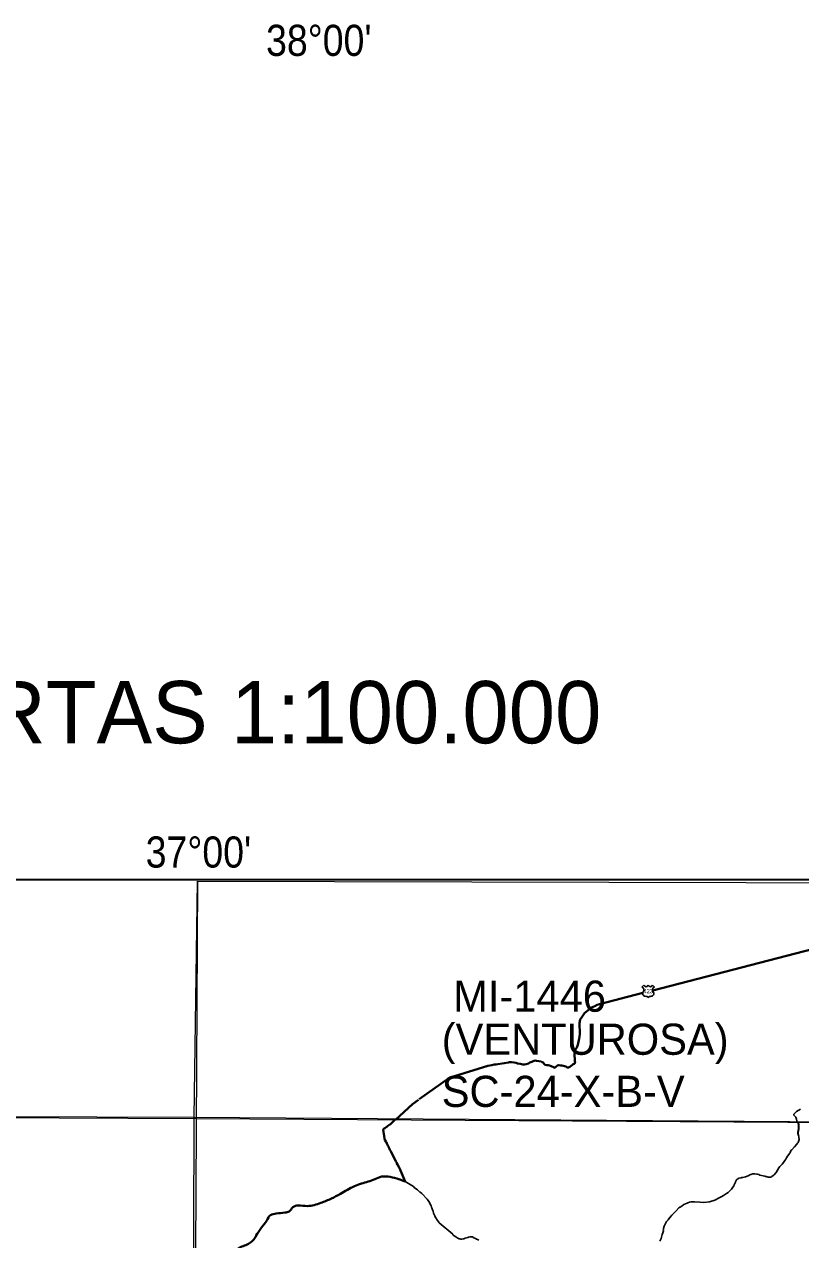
# Model space of a CAD drawing. Extents: x 553962 to 842807, y 8883888 to 9032388.
# Drawn here: x 604874 to 617340, y 8918990 to 8938500 of the extents above; entities that cross this region are included whole.
import ezdxf
from ezdxf.enums import TextEntityAlignment as Align

# ---------------------------------------------------------------- set-up
doc = ezdxf.new("R2010")
doc.units = 0
doc.header["$LTSCALE"] = 150
doc.layers.add('46', color=7, linetype='Continuous')
doc.layers.add('6', color=7, linetype='Continuous', lineweight=13)

msp = doc.modelspace()

# ---------------------------------------------------------------- linework, layer by layer
at = {"layer": '6', "lineweight": 25}
for p, q in [((614790.2, 8923043.1), (614822.1, 8923075.1)), ((614962, 8923075.1), (614994, 8923043.1))]:
    msp.add_line(p, q, dxfattribs=at)
at = {"layer": '6', "lineweight": 35}
msp.add_lwpolyline([(574695.3, 8924769.6), (626625.7, 8924769.6), (626625.7, 8896026.7), (574695.3, 8896026.7)], close=True, dxfattribs=at)
at = {"layer": '6'}
for points in [[(607657.7, 8924743.3), (607574.2, 8909874.9), (607492.3, 8896026.7)], [(574684.9, 8921064.7), (596639.8, 8920989.8), (607636.3, 8920937.2), (626625.7, 8920820.5)], [(608653.2, 8919135.4), (608627.5, 8919108.1), (608598.7, 8919080.5), (608588.5, 8919064.1), (608579.3, 8919042.5), (608574.7, 8919033.7)]]:
    msp.add_lwpolyline(points, dxfattribs=at)
for points in [[(607657.7, 8924743.3), (618663, 8924716.1), (618636, 8920869.6), (607600.8, 8920952.4)], [(607600.8, 8920952.4), (596639.8, 8920989.8), (596608.8, 8909934.4), (607569.8, 8909894.9)]]:
    msp.add_lwpolyline(points, close=True, dxfattribs=at)
at = {"layer": '6', "lineweight": 40}
for points in [[(614964.2, 8922992.9), (617832.6, 8923732.6)], [(611214.5, 8921246.7), (611690.9, 8921581.7), (611739.2, 8921604.7), (611780.6, 8921615.4), (612315.8, 8921783.7), (612380.5, 8921791.8), (612418.8, 8921801.5), (612446.2, 8921801.9), (612579.5, 8921823.3), (612649.2, 8921836.5), (612665.4, 8921838.8), (612696.8, 8921839.3), (612734.3, 8921834.8), (612769.8, 8921828.3), (612794.3, 8921820.6), (612836.9, 8921811.2), (612878.6, 8921802.8), (612904.9, 8921800.2), (612931.2, 8921805.6), (612968.5, 8921819.4), (612991.5, 8921833.9), (613020.7, 8921847.5), (613043.9, 8921853.9), (613078.2, 8921864.6), (613100.5, 8921863.9), (613172.6, 8921848.9), (613187.9, 8921842.1), (613203.2, 8921832.2), (613213.5, 8921824.3), (613217.6, 8921816.3), (613223.8, 8921806.3), (613239.2, 8921795.4), (613263.6, 8921790.7), (613283.8, 8921790), (613306.2, 8921786.3), (613333.6, 8921777.7), (613370.4, 8921757.1), (613391.7, 8921751.3), (613410.8, 8921764.8), (613432.7, 8921788.4), (613459, 8921792.8), (613487.4, 8921786.2), (613506.7, 8921785.5), (613523.9, 8921782.7), (613547.3, 8921778.1), (613567.7, 8921770.3), (613590.2, 8921755.5), (613610.5, 8921752.8), (613631.6, 8921763.2), (613655.6, 8921783.8), (613674.6, 8921799.3), (613688.6, 8921808.6), (613703.7, 8921814.9), (613713.7, 8921824.2), (613717.6, 8921837.4), (613713.3, 8921852.5), (613712.8, 8921885.8), (613707.8, 8921948.4), (613715.8, 8922026.4), (613743.5, 8922073.3), (613761, 8922118.1), (613780.1, 8922192.2), (613785.2, 8922213.2), (613792, 8922289.4), (613792.2, 8922338.9), (613787.9, 8922425.8), (613790.3, 8922468.3), (613797.6, 8922523), (613826.5, 8922560.8), (613869.1, 8922624.2), (613980.1, 8922716.9), (614036.5, 8922740.1), (614074.7, 8922760.9), (614109.9, 8922772.6), (614804.5, 8922951.7)], [(611201.4, 8921234.4), (611108.7, 8921166), (610832.8, 8920916.1)], [(610827.8, 8920917.6), (610823, 8920914), (610762.1, 8920855.7), (610749.5, 8920841.5), (610740.9, 8920836.9), (610713, 8920816.2), (610698.2, 8920806.3), (610662.6, 8920780.4), (610653.5, 8920774.9), (610648.2, 8920770.6), (610634.6, 8920757.1)], [(610634.6, 8920757.1), (610655.2, 8920612.5), (610665.4, 8920591.1), (610678.2, 8920567.9), (610682, 8920558.9), (610694.4, 8920535.7), (610709.7, 8920504), (610719.3, 8920486.7), (610726, 8920471.9), (610739.4, 8920447.4), (610745.8, 8920433.2), (610758.2, 8920410.6), (610809.7, 8920308.8), (610840.7, 8920249.1), (610850, 8920232.8), (610852.7, 8920225.4), (610867.4, 8920199.1), (610898.1, 8920137.8), (610910.3, 8920115.9), (610916.7, 8920101.6), (610989.7, 8919925.2)]]:
    msp.add_lwpolyline(points, dxfattribs=at)
at = {"layer": '6', "lineweight": 25}
for points in [[(617334.2, 8921086.1), (617270.4, 8921047), (617247.5, 8921019.3), (617230.5, 8921004.9), (617231.8, 8920988.8), (617263.7, 8920954.9), (617272.2, 8920926.8), (617283, 8920878)], [(617303, 8920665.4), (617309.3, 8920639.1), (617311.5, 8920622.3), (617313.5, 8920613.9), (617313.6, 8920598.5), (617309.4, 8920583), (617298.1, 8920552.1), (617290.2, 8920537.8), (617278.2, 8920522.3), (617239.5, 8920482.6), (617196.2, 8920435), (617188.5, 8920425.5), (617182.5, 8920416.2), (617169.7, 8920388.5), (617163.2, 8920380.5), (617127.8, 8920330.6), (617112.8, 8920304.9), (617101.5, 8920282.3), (617087.7, 8920260.7), (617065.5, 8920231.4), (617042.8, 8920204.7), (617013.1, 8920175.2), (617003.5, 8920164.7), (616988.6, 8920143.8), (616945.6, 8920070.1), (616939.6, 8920064.2), (616914.7, 8920032.8), (616900.5, 8920019.1), (616878.8, 8920003.5), (616863.5, 8919995.6), (616858.6, 8919994.5), (616837.8, 8919993.2), (616816.9, 8919996.3), (616783.4, 8920002.8), (616773, 8920006.6), (616763.5, 8920011.1), (616735.6, 8920015.5), (616683.6, 8920028.8), (616669.3, 8920035.2), (616647.7, 8920042.1), (616635, 8920043.9), (616602.2, 8920045.9), (616583.8, 8920046.3), (616574.1, 8920045.7), (616539, 8920038.2), (616523, 8920032.3), (616509.2, 8920023.2), (616495.5, 8920017.5)], [(616495.5, 8920017.5), (616453.3, 8920000), (616409.4, 8919988.9), (616397.5, 8919986.6), (616384.8, 8919985.4), (616353, 8919979.2), (616343.8, 8919975.8), (616333.6, 8919969.7), (616322.5, 8919960.4), (616311.1, 8919948.7), (616302.5, 8919938.1), (616291.5, 8919919.8), (616291, 8919912.9), (616282.8, 8919891.9), (616271.9, 8919869.4), (616271.1, 8919865.5), (616268.5, 8919861.9), (616266.1, 8919856.8), (616238.5, 8919814.9), (616227.3, 8919799.4), (616193, 8919764.1), (616173.5, 8919748.5), (616148.1, 8919730.4), (616131, 8919720.4), (616100.8, 8919700.3), (616073.8, 8919685.1), (616060.5, 8919679.7), (616039.2, 8919669)], [(610989.7, 8919925.2), (611098.4, 8919862.7), (611123, 8919843.5), (611135.6, 8919830.6), (611185.4, 8919791.8), (611226, 8919753.4), (611227.9, 8919750.7), (611254.6, 8919731.6), (611274, 8919715.5), (611334.2, 8919651.6), (611344.9, 8919639.3), (611360, 8919618.6), (611370.7, 8919602.3), (611407.8, 8919535.5), (611413.8, 8919514.2), (611418, 8919503.3), (611429.4, 8919467.6), (611437.3, 8919447.9), (611446.9, 8919416.8), (611465.8, 8919371.6)], [(616039.2, 8919669), (615963.3, 8919626.9), (615874.3, 8919597.3), (615786, 8919586), (615718.6, 8919590.7), (615634.3, 8919599.2), (615608.5, 8919599.2), (615576.6, 8919596), (615554.8, 8919590.4), (615530.2, 8919581.5), (615515.4, 8919577.2), (615465.2, 8919552.7), (615436.7, 8919533.6), (615420.6, 8919524.9), (615405.8, 8919513.6), (615400, 8919511.3), (615384.8, 8919499.5), (615340.1, 8919452.8), (615328, 8919441.6), (615316.8, 8919433.2), (615291.1, 8919406.3), (615270.9, 8919383.5), (615241.8, 8919353.8), (615220.6, 8919327.1), (615210.8, 8919311.4), (615187.3, 8919281.6), (615162.8, 8919242), (615149.2, 8919208.9), (615137.5, 8919168), (615134.8, 8919161.3), (615133.6, 8919146.7), (615134.7, 8919133.5), (615126.3, 8919098.2), (615118.1, 8919074.2), (615109.5, 8919052.6), (615097.1, 8919008.6), (615080.7, 8918964.7)], [(611465.8, 8919371.6), (611476.9, 8919345.1), (611479.5, 8919342.7), (611508.7, 8919298.4), (611528.6, 8919273.8), (611536.4, 8919259)], [(611536.4, 8919259), (611753.5, 8919076.8), (611755.2, 8919073), (611761.1, 8919065.5), (611773.8, 8919054.2), (611802.2, 8919035.3), (611833, 8919017.3), (611858.2, 8919004.8), (611866.1, 8919002.4), (611884.7, 8919000), (611901.9, 8918999.7), (611921, 8919002.9), (611932.1, 8919006.5), (611951.6, 8919014.3), (611971.8, 8919020.1), (611994.5, 8919028.2), (612003.8, 8919030.8), (612029.9, 8919036)], [(612029.9, 8919036), (612040.2, 8919038.1), (612047.4, 8919038.5), (612058.4, 8919036.9)], [(612058.4, 8919036.9), (612068.4, 8919035.4), (612079.1, 8919029), (612083.1, 8919027)], [(612083.1, 8919027), (612129.9, 8919004.2), (612137, 8918999.2), (612151.9, 8918992.2), (612169.6, 8918981.6)]]:
    msp.add_lwpolyline(points, dxfattribs=at)
at = {"layer": '6', "lineweight": 35}
msp.add_lwpolyline([(617294.2, 8920878.4), (617302.4, 8920840.9), (617306.5, 8920803.1), (617306.1, 8920783.9), (617304, 8920766.2), (617295.2, 8920713.2), (617295.4, 8920693.6), (617300.5, 8920675.8), (617303, 8920665.4)], dxfattribs=at)
at = {"layer": '6', "lineweight": 25}
for centre, radius, start, end in [((614777.7, 8922998.7), 46.1, 317.5721, 74.36886), ((614848.4, 8922941.7), 44.9, 144.73733, 264.65778), ((614857.1, 8923088.5), 37.4, 200.95927, 339.04073), ((614927, 8923088.5), 37.4, 200.95927, 339.04073), ((614935.7, 8922941.7), 44.9, 275.34222, 35.26267), ((615006.4, 8922998.7), 46.1, 105.62774, 222.4279), ((614844, 8922779), 118, 72.89371, 89.90057), ((614873.2, 8922873.7), 18.9, 357.69345, 72.92955), ((614910.9, 8922873.7), 18.9, 107.07045, 182.30655), ((614940.1, 8922779), 118, 90.09943, 107.10629)]:
    msp.add_arc(centre, radius, start, end, dxfattribs=at)
at = {"layer": '6', "lineweight": 40}
msp.add_spline([(605233.4, 8918291.8), (605425.1, 8918291.8), (605556.8, 8918274.6), (605694.1, 8918217.3), (605780, 8918168.6), (605911.6, 8918165.8), (606008.9, 8918211.6), (606114.8, 8918211.6), (606197.8, 8918134.3), (606353.7, 8918138.6), (606551.2, 8918198.7), (606637.1, 8918198.7), (606903.2, 8918104.2), (607195.1, 8918130), (607418.3, 8918172.9), (607555.7, 8918130), (607658.7, 8918138.6), (607753.1, 8918172.9), (607813.2, 8918172.9), (607967.8, 8918353.3), (608139.5, 8918542.3), (608208.1, 8918748.4), (608345.5, 8918868.7), (608508.6, 8918946), (608680.3, 8919186.5), (608766.2, 8919298.2), (608826.3, 8919384.1), (608920.7, 8919409.8), (609058.1, 8919427), (609126.8, 8919444.2), (609186.8, 8919512.9), (609272.7, 8919538.7), (609418.7, 8919530.1), (609633.3, 8919581.6), (609805, 8919650.3), (609950.9, 8919727.6), (610174.2, 8919847.9), (610285.8, 8919890.8), (610500.4, 8919959.5), (610612, 8920002.5), (610715, 8920002.5), (610989.7, 8919925.2)], degree=3, dxfattribs=at)

# ---------------------------------------------------------------- texts
at = {"layer": '46', "width": 0.9}
msp.add_text("38°00'", height=500, dxfattribs=at).set_placement((609602.8, 8937992.5), align=Align.CENTER)
at = {"layer": '6'}
msp.add_text('ARTICULAÇÃO DAS CARTAS 1:100.000', height=1000, dxfattribs=at).set_placement((601765.5, 8926958.2), align=Align.CENTER)
for s, height, width, p in [("37°00'", 500, 0.9, (607670.1, 8924963.2)), ('423', 70, 0.75, (614892.5, 8922945.5))]:
    msp.add_text(s, height=height, dxfattribs=dict(at, width=width)).set_placement(p, align=Align.CENTER)
for s, p in [('MI-1446', (611760.8, 8922649.4)), ('(VENTUROSA)', (611576.4, 8921958.6)), ('SC-24-X-B-V', (611576.4, 8921121.5))]:
    msp.add_text(s, height=500, dxfattribs=at).set_placement(p)

doc.saveas('drawing.dxf')
